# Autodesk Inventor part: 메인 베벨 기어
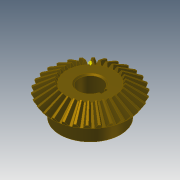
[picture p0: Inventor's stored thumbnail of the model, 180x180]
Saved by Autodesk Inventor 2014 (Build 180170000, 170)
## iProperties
Created: 2014-10
Part Number: 메인 베벨 기어
Material: 강철
Document SubType Name: Modeling
Designer: KYOUNG IL JANG
Categories: <?xml version="1.0" encoding="UTF-16"?> <MemberInstance><Categories><FamilyTemplate><FamilyTemplateParameter ValueType="xs:double" Id="1" ObjectReferenceKey="da
Mass: 269.24 g
Surface Area: 108.837 cm^2
Volume: 34.2981 cm^3
Density: 7.85 g/cm^3
Appearance: 얼룩무늬
CustomPartVersion: 1
Company: 한국ATC센터
Author: KYOUNG IL JANG
Revision Number: 1
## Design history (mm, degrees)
node "맨 위 점"
node "메쉬 평면2"
sketch "톱니 본체 스케치"
  geometry: L1 (0, 0)-(28.669, -21.997); L2 (28.669, -21.997)-(31.109, -18.336); L3 (31.109, -18.336)-(0, 0); L4 (30, -20)-(0, 0); L5 (17.219, -13.212)-(18.685, -11.013); L6 (28.669, -21.997)-(17.219, -13.212); L7 (31.109, -18.336)-(18.685, -11.013); L8 (0, -39.387)-(0, 6.564) reference; L9 (0, -20)-(31.109, -20)
  constraints: 16 end point, 4 point on line, 3 perpendicular, 2 collinear, 1 horizontal alignment, 1 vertical alignment
  dimensions: "d0" = 60 diameter of L4.start L8 (= da_de); "d1" = 57.33744 diameter of L1.end L8 (= da_dfe); "d2" = 62.2188 diameter of L2.end L8 (= da_dae); "d3" = 14.4 distance between parallel lines of L2 L5 (= da_b); "d4" = 18.3359 vertical distance of L2.end L1.start (= da_ve)
revolve "톱니 본체" sketch "톱니 본체 스케치" stored, may be unused: angle "d5" = 90 deg
node "시작점"
node "톱니 평면"
sketch "시작 스케치"
  geometry: L1 (0, -23.505)-(0, 10.645) reference; L2 (-0.709, -2.928)-(0.709, -2.928); A1 r 19.188 centre (-19.457, -7.014) between (-0.709, -2.928) and (-3.232, 3.229); A2 r 19.188 centre (19.457, -7.014) between (3.232, 3.229) and (0.709, -2.928); A3 r 57.403 centre (0, -54.083) between (3.232, 3.229) and (-3.232, 3.229); 1 further point
  constraints: 6 point on circle, 3 centre point, 3 symmetric about line, 2 end point, 1 coincident, 1 perpendicular, 1 other
  dimensions: "d7" = 19.18795 radius of A1 (= fd_rr); "d8" = 19.45712 horizontal distance of point (0, -54.083) A1.centre (= fd_x); "d9" = 47.06905 vertical distance of point (0, -54.083) A1.centre (= fd_y); "d57" = 57.40327 radius of A3 (= 0.5 x fd_dva + 0.3 x da_he); "d58" = 51.15527 distance from line of A3.centre L2 (= 0.5 x fd_dva - 1.12 x da_he)
node "끝점"
  node "끝 평면"
sketch "3D 스케치 오른쪽"
  node "Helical Curve Right" dims "d65" = 229.90621 (computed from da_dm, da_delta, da_beta), "d66" = 31.5, "d67" = 60 (= da_de), "d68" = -9.82794 (= -da_delta), "d69" = 8.10972 (computed from fd_loft, da_delta)
node "끝 평면 오른쪽"
sketch "끝 스케치 오른쪽"
  geometry: L1 (0, -41.54)-(0, 13.178) reference; L2 (-0.422, -1.69)-(0.422, -1.69); A1 r 11.427 centre (-11.587, -4.123) between (-0.422, -1.69) and (-1.925, 1.977); A2 r 11.427 centre (11.587, -4.123) between (1.925, 1.977) and (0.422, -1.69); A3 r 34.184 centre (0, -32.153) between (1.925, 1.977) and (-1.925, 1.977); 1 further point
  constraints: 6 point on circle, 3 centre point, 3 symmetric about line, 2 end point, 1 coincident, 1 perpendicular, 1 other
  dimensions: "d70" = 11.58699 horizontal distance of A3.centre A1.centre (computed from fd_x, fd_ratio); "d71" = 28.03028 vertical distance of point (0, -32.153) A1.centre (computed from fd_y, fd_ratio); "d72" = 11.4267 radius of A1 (computed from fd_rr, fd_ratio); "d73" = 30.46369 distance from line of point (0, -32.153) L2 (computed from d58, fd_ratio); "d74" = 34.18446 radius of A3 (computed from d57, fd_ratio)
feature "로프트 오른쪽" sketch "끝 스케치 오른쪽" dims "d75" = 0, "d77" = 0, "d79" = 0, "d80" = 90 deg, "d85" = 20, "d92" = 90 deg, "d93" = 90 deg, "da_teethtype" = 0 [user parameter]
sketch "3D 스케치 왼쪽"
  node "Helical Curve Left" dims "d26" = 229.90621 (computed from da_dm, da_delta, da_beta), "d27" = 8.10972 (computed from fd_loft, da_delta), "d28" = 60 (= da_de), "d29" = -9.82794 (= -da_delta)
node "끝 평면 왼쪽"
sketch "끝 스케치 왼쪽" dims "d56" = 10.3728 (derived)
  geometry: L1 (0, -43.753)-(0, 15.405) reference; L2 (-0.422, -1.678)-(0.422, -1.678); A1 r 11.427 centre (-11.587, -4.111) between (-0.422, -1.678) and (-1.925, 1.988); A2 r 11.427 centre (11.587, -4.111) between (1.925, 1.988) and (0.422, -1.678); A3 r 34.184 centre (0, -32.142) between (1.925, 1.988) and (-1.925, 1.988); 2 further points; 1 other entity
  constraints: 6 point on circle, 3 centre point, 3 symmetric about line, 2 end point, 1 coincident, 2 other
  dimensions: "d30" = 11.4267 radius of A1 (computed from fd_rr, fd_ratio); "d31" = 11.58699 horizontal distance of point (0, -32.142) A1.centre (computed from fd_x, fd_ratio); "d32" = 28.03028 vertical distance of A1.centre point (0, -32.142) (computed from fd_y, fd_ratio); "d61" = 34.18446 radius of A3 (computed from d57, fd_ratio); "d62" = 30.46369 distance from line of point (0, -32.142) L2 (computed from d58, fd_ratio)
feature "로프트 왼쪽" sketch "끝 스케치 왼쪽" dims "d35" = 0, "d37" = 0, "d39" = 0, "d40" = 90 deg, "d84" = 10, "d90" = 90 deg, "d91" = 90 deg, "da_teethtype" = 0 [user parameter]
sketch "본체 스케치"
  geometry: L1 (0, -35.038)-(0, -19.531) reference; L2 (28.669, -21.997)-(17.219, -13.212) reference; L3 (17.219, -13.212)-(0, -13.212); L4 (28.669, -21.997)-(0, -21.997)
  constraints: 4 end point, 2 perpendicular, 2 point on line
revolve "본체 고정" sketch "본체 스케치" stored, may be unused: angle "d46" = 90 deg
feature "피치 지름" dims angle "d47" = 90 deg
sketch "스케치8"
  geometry: C1 r 22.5 at (0, 0); 1 further point
  constraints: 1 centre point, 1 coincident
  dimensions: "d94" = 45 diameter of C1
extrude "돌출1" join sketch "스케치8" distance "d95" = 13; taper "d96" = 0 deg
sketch "스케치9"
  geometry: 1 further point
hole "구멍1" sketch "스케치9" at (0, 0) diameter "d97" = 17; stored, may be unused: countersink angle "d101" = 90 deg, drill point angle "d103" = 118 deg; dims "d98" = 6, "d99" = 4, "d100" = 2, "d102" = 8
sketch "스케치10"
  geometry: L1 (8.124, 2.5)-(10.8, 2.5); L2 (10.8, 2.5)-(10.8, -2.5); L3 (10.8, -2.5)-(8.124, -2.5); A1 r 8.5 centre (0, 0) between (8.124, 2.5) and (8.124, -2.5) reference; 1 further point
  constraints: 6 end point, 2 parallel, 2 point on circle, 1 horizontal, 1 perpendicular
  dimensions: "d104" = 5 distance of L1.end L2.end; "d112" = 19.3 dimension on A1 L2
extrude "돌출2" cut sketch "스케치10" stored distance "d106" = 10; taper "d107" = 0 deg
chamfer "모따기1" distance "d108" = 1; stored, may be unused: second distance "d109" = 2, angle "d110" = 45 deg
fillet "모깎기1" dims "d111" = 2
body "Solid1"
feature "로프트" dims "d17" = 0, "d18" = 90 deg, "d19" = 0, "d20" = 90 deg, "d89" = 0, "da_teethtype" = 0 [user parameter]
pattern_circular "원형 패턴" dims angle "d22" = 360 deg, "d88" = 0, "da_teethtype" = 0 [user parameter]
pattern_circular "원형 패턴 오른쪽" dims angle "d82" = 360 deg, "da_teethtype" = 0 [user parameter]
pattern_circular "원형 패턴 왼쪽" dims angle "d42" = 360 deg, "da_teethtype" = 0 [user parameter]
sketch "끝 스케치"
  geometry: L1 (0, -15.359)-(0, 6.983) reference; L2 (-0.422, -1.69)-(0.422, -1.69); A1 r 11.427 centre (-11.587, -4.123) between (-0.422, -1.69) and (-1.925, 1.977); A2 r 11.427 centre (11.587, -4.123) between (1.925, 1.977) and (0.422, -1.69); A3 r 34.184 centre (0, -32.153) between (1.925, 1.977) and (-1.925, 1.977); 1 further point
  constraints: 6 point on circle, 3 centre point, 3 symmetric about line, 2 end point, 1 coincident, 1 other
  dimensions: "d12" = 11.4267 radius of A1 (computed from fd_rr, fd_ratio); "d15" = 11.58699 horizontal distance of A1.centre point (0, -32.153) (computed from fd_x, fd_ratio); "d16" = 28.03028 vertical distance of A1.centre point (0, -32.153) (computed from fd_y, fd_ratio); "d59" = 34.18446 radius of A3 (computed from d57, fd_ratio); "d60" = 30.46369 distance from line of A3.centre L2 (computed from d58, fd_ratio)
sketch "Sketch6"
  geometry: L1 (30, -20)-(0, 0) reference; L2 (0, -37.8)-(0, 6.3) reference
body "Srf1"
other parameters: "da_b" = 14.4 [user parameter; used in 2 equation terms], "da_de" = 60 [user parameter; used in 4 equation terms], "da_dae" = 62.2188 [user parameter; used in 2 equation terms], "da_dfe" = 57.33744 [user parameter; used in 1 equation term], "da_le" = 36.05551 [user parameter; used in 1 equation term], "da_omega" = 90 deg [user parameter; used in 1 equation term], "da_beta" = 0 [user parameter; used in 2 equation terms], "da_delta" = 9.82794 [user parameter; used in 8 equation terms], "da_alpha" = 20 deg [user parameter; used in 2 equation terms], "da_he" = 4.4 [user parameter; used in 4 equation terms], "da_ve" = 18.3359 [user parameter; used in 1 equation term], "fd_dv" = 108.16654 (computed from da_de, da_delta) [user parameter; used in 1 equation term], "fd_dva" = 112.16654 (computed from da_dae, da_delta) [user parameter; used in 3 equation terms], "fd_dvb" = 101.6433 (computed from fd_dv, da_alpha) [user parameter; used in 2 equation terms], "da_zv" = 540.83269 [user parameter; used in 1 equation term], "fd_loft" = 14.62 (= da_b + 0.05 x da_he) [user parameter; used in 4 equation terms], "fd_ratio" = 5.95514 (computed from da_le, fd_loft) [user parameter; used in 15 equation terms], "fd_rr" = 19.18795 (computed from fd_dd, fd_dvb) [user parameter; used in 6 equation terms], "fd_angle" = 0.29367 (computed from da_zv) [user parameter; used in 4 equation terms], "fd_x1" = 1.58802 (computed from da_dvw, fd_angle) [user parameter; used in 1 equation term], "fd_y1" = 54.05995 (computed from da_dvw, fd_angle) [user parameter; used in 1 equation term], "fd_x2" = 17.8691 (computed from fd_rr, fd_angle2, fd_angle) [user parameter; used in 1 equation term], "fd_y2" = 6.9909 (computed from fd_rr, fd_angle2, fd_angle) [user parameter; used in 1 equation term], "fd_x" = 19.45712 (= fd_x1 + fd_x2) [user parameter; used in 4 equation terms], "fd_y" = 47.06905 (= fd_y1 - fd_y2) [user parameter; used in 4 equation terms], "fd_angle2" = 3.43555 (computed from fd_dvb, fd_dd, da_alpha) [user parameter; used in 2 equation terms], "fd_dd" = 108.64654 (= fd_dva - 0.8 x da_he) [user parameter; used in 2 equation terms], "da_dvw" = 108.16654 [user parameter; used in 2 equation terms], "d11" = 14.62 (= fd_loft), "da_dm" = 48.01848 [user parameter; used in 2 equation terms], "da_x" = 0 [user parameter], "da_m" = 2 [user parameter], "d48" = 0, "d49" = 0, "d50" = 90 deg (= da_omega), "d51" = 6 deg (computed from da_z), "d52" = 0, "d53" = 0, "d54" = 0
